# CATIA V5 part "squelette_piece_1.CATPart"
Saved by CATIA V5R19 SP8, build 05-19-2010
Part number: squelette_piece_1
Publications: "Point.10", "Point.9", "Point.8", "Point.7", "Point.6", "Point.5", "Droite.3", "Point.4", "Point.3", "Droite.2", "Point.2", "Point.1", "Droite.1"
Bounding box of the stored display mesh (mm): x -15 to 20, y 63.5 to 198.2, z -634.7 to 0
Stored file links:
  G:\EU_thinkMotion\CFAO_2010\SIL_groupe1\SIL_groupe1\A reprendre\lalpha\lalpha\Alpha.mécanisme\squelette_piece_1.CATPart
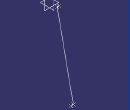
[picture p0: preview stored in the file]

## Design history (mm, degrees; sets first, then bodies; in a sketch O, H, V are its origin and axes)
Set1
  Line1: type PtPt, FirstPoint Point1, SecondPoint Point2
  Point1: stored without definition
  Point2: stored without definition
  Line2: type PtPt, FirstPoint Point3, SecondPoint Point4
  Point3: stored without definition
  Point4: stored without definition
  Line3: type PtPt, FirstPoint Point5, SecondPoint Point6
  Point5: stored without definition
  Point6: stored without definition
  Point7: (0, 0, 0), relative to Point8
  Point8: stored without definition
  Point9: (0, 0, 0), relative to Point10
  Point10: stored without definition
Body1 (main body)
